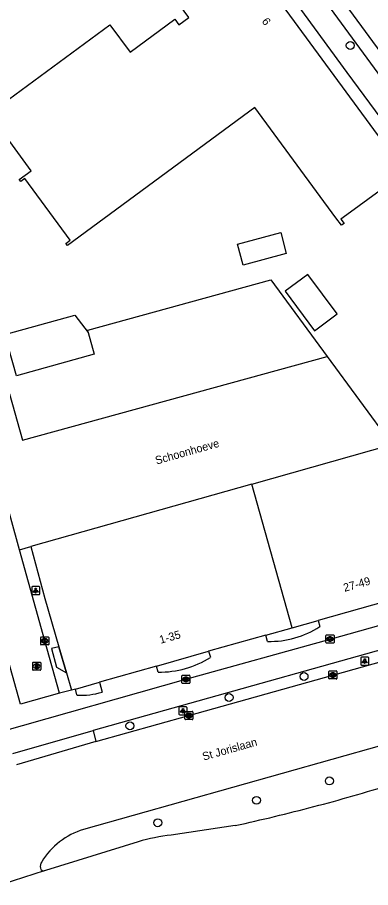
# Model space of a CAD drawing. Extents: x 161801 to 162379, y 382315 to 382832.
# Drawn here: x 161942.5 to 161986.3, y 382338.2 to 382446.1 of the extents above; entities that cross this region are included whole.
import ezdxf

# ---------------------------------------------------------------- set-up
doc = ezdxf.new("R2010")
doc.units = 0
for name, color, linetype in [('IMGEO_Boom', 7, 'Continuous'), ('IMGEO_Fietspad_open', 7, 'Continuous'), ('IMGEO_Hek', 7, 'Continuous'), ('IMGEO_Kolk', 7, 'Continuous'), ('IMGEO_Lichtpunt', 7, 'Continuous'), ('IMGEO_Openbare_ruimte_label', 7, 'Continuous'), ('IMGEO_Pand', 7, 'Continuous'), ('IMGEO_Pand_nummerreeks', 7, 'Continuous'), ('IMGEO_Pand_overbouw', 7, 'Continuous'), ('IMGEO_Parkeervlak_open', 7, 'Continuous'), ('IMGEO_Rijbaan_lokaal_gesloten', 7, 'Continuous'), ('IMGEO_Rijbaan_lokaal_open', 7, 'Continuous'), ('IMGEO_Rioolput', 7, 'Continuous'), ('IMGEO_Voetpad_open', 7, 'Continuous')]:
    doc.layers.add(name, color=color, linetype=linetype)

msp = doc.modelspace()

# ---------------------------------------------------------------- linework, layer by layer
at = {"layer": 'IMGEO_Boom'}
for centre in [(161983.8, 382442.62), (161978.07, 382364.4), (161968.77, 382361.8), (161956.46, 382358.28), (161981.22, 382351.46), (161972.17, 382349.05), (161959.92, 382346.27)]:
    msp.add_circle(centre, 0.489, dxfattribs=at)
at = {"layer": 'IMGEO_Fietspad_open'}
for points in [[(161923.26, 382352.78), (161924.44, 382353.11), (161940.37, 382357.56), (161963.41, 382364.05), (161981.29, 382369.04), (162000, 382374.27), (162016.84, 382378.99), (162027.28, 382381.95)], [(162003.49, 382372.17), (162002.74, 382371.95), (162000, 382371.17), (161951.89, 382357.7)], [(161941.94, 382354.87), (161951.89, 382357.7)]]:
    msp.add_lwpolyline(points, dxfattribs=at)
at = {"layer": 'IMGEO_Hek'}
for points in [[(161980.93, 382404.08), (161988.98, 382393.14)], [(161942.76, 382380.12), (161944.18, 382380.53)]]:
    msp.add_lwpolyline(points, dxfattribs=at)
at = {"layer": 'IMGEO_Kolk'}
for p, q in [((161980.79, 382368.62), (161980.79, 382369.47)), ((161980.87, 382369.55), (161981.72, 382369.55)), ((161981.79, 382369.47), (161981.79, 382368.62)), ((161945.39, 382368.38), (161945.39, 382369.23)), ((161945.47, 382369.31), (161946.32, 382369.31)), ((161946.32, 382368.31), (161945.47, 382368.31)), ((161945.88, 382369.09), (161945.91, 382369.09)), ((161945.9, 382368.53), (161945.88, 382368.53)), ((161946.4, 382369.23), (161946.4, 382368.38)), ((161981.72, 382368.55), (161980.87, 382368.55)), ((161981.28, 382369.33), (161981.31, 382369.33)), ((161981.3, 382368.77), (161981.28, 382368.77)), ((161981.22, 382365.09), (161982.07, 382365.09)), ((161962.91, 382363.63), (161962.91, 382364.48)), ((161962.98, 382364.55), (161963.84, 382364.55)), ((161963.4, 382364.33), (161963.42, 382364.33)), ((161963.91, 382364.48), (161963.91, 382363.63)), ((161981.14, 382364.16), (161981.14, 382365.01)), ((161982.07, 382364.09), (161981.22, 382364.09)), ((161981.63, 382364.87), (161981.66, 382364.87)), ((161981.65, 382364.31), (161981.63, 382364.31)), ((161982.14, 382365.01), (161982.14, 382364.16)), ((161963.84, 382363.55), (161962.98, 382363.55)), ((161963.42, 382363.77), (161963.39, 382363.77)), ((161963.28, 382359.14), (161963.28, 382359.99)), ((161963.35, 382360.07), (161964.21, 382360.07)), ((161963.77, 382359.84), (161963.79, 382359.84)), ((161964.28, 382359.99), (161964.28, 382359.14)), ((161964.21, 382359.06), (161963.35, 382359.06)), ((161963.79, 382359.29), (161963.76, 382359.29))]:
    msp.add_line(p, q, dxfattribs=at)
for points in [[(161980.79, 382368.62), (161980.79, 382369.47)], [(161980.87, 382369.55), (161981.72, 382369.55)], [(161981.79, 382369.47), (161981.79, 382368.62)], [(161945.39, 382368.38), (161945.39, 382369.23)], [(161945.47, 382369.31), (161946.32, 382369.31)], [(161946.32, 382368.31), (161945.47, 382368.31)], [(161945.71, 382369.01), (161945.84, 382369.01), (161945.84, 382368.86), (161945.97, 382369.01), (161946.13, 382369.01), (161945.99, 382368.86), (161946.14, 382368.61), (161945.99, 382368.61), (161945.9, 382368.77), (161945.84, 382368.71), (161945.84, 382368.61), (161945.71, 382368.61), (161945.71, 382369.01)], [(161946.4, 382369.23), (161946.4, 382368.38)], [(161981.72, 382368.55), (161980.87, 382368.55)], [(161981.11, 382369.25), (161981.24, 382369.25), (161981.24, 382369.09), (161981.37, 382369.25), (161981.53, 382369.25), (161981.39, 382369.1), (161981.54, 382368.85), (161981.39, 382368.85), (161981.3, 382369.01), (161981.24, 382368.94), (161981.24, 382368.85), (161981.11, 382368.85), (161981.11, 382369.25)], [(161981.22, 382365.09), (161982.07, 382365.09)], [(161962.91, 382363.63), (161962.91, 382364.48)], [(161962.98, 382364.55), (161963.84, 382364.55)], [(161963.23, 382364.25), (161963.35, 382364.25), (161963.35, 382364.1), (161963.48, 382364.25), (161963.65, 382364.25), (161963.5, 382364.1), (161963.65, 382363.85), (161963.5, 382363.85), (161963.42, 382364.02), (161963.35, 382363.95), (161963.35, 382363.85), (161963.23, 382363.85), (161963.23, 382364.25)], [(161963.91, 382364.48), (161963.91, 382363.63)], [(161981.14, 382364.16), (161981.14, 382365.01)], [(161982.07, 382364.09), (161981.22, 382364.09)], [(161981.46, 382364.79), (161981.59, 382364.79), (161981.59, 382364.63), (161981.72, 382364.79), (161981.88, 382364.79), (161981.74, 382364.64), (161981.89, 382364.39), (161981.74, 382364.39), (161981.65, 382364.55), (161981.59, 382364.48), (161981.59, 382364.39), (161981.46, 382364.39), (161981.46, 382364.79)], [(161982.14, 382365.01), (161982.14, 382364.16)], [(161963.84, 382363.55), (161962.98, 382363.55)], [(161963.28, 382359.14), (161963.28, 382359.99)], [(161963.35, 382360.07), (161964.21, 382360.07)], [(161963.6, 382359.76), (161963.72, 382359.76), (161963.72, 382359.61), (161963.85, 382359.76), (161964.02, 382359.76), (161963.87, 382359.61), (161964.02, 382359.36), (161963.87, 382359.36), (161963.79, 382359.53), (161963.72, 382359.46), (161963.72, 382359.36), (161963.6, 382359.36), (161963.6, 382359.76)], [(161964.28, 382359.99), (161964.28, 382359.14)], [(161964.21, 382359.06), (161963.35, 382359.06)]]:
    msp.add_lwpolyline(points, dxfattribs=at)
for centre, start, end in [((161980.87, 382369.47), 91.552, 178.448), ((161980.87, 382369.47), 91.552, 178.448), ((161981.72, 382369.47), 1.552, 88.448), ((161981.72, 382369.47), 1.552, 88.448), ((161945.47, 382369.23), 91.552, 178.448), ((161945.47, 382369.23), 91.552, 178.448), ((161945.47, 382368.38), 181.552, 268.448), ((161945.47, 382368.38), 181.552, 268.448), ((161946.32, 382369.23), 1.552, 88.448), ((161946.32, 382369.23), 1.552, 88.448), ((161946.32, 382368.38), 271.552, 358.448), ((161946.32, 382368.38), 271.552, 358.448), ((161980.87, 382368.62), 181.552, 268.448), ((161980.87, 382368.62), 181.552, 268.448), ((161981.72, 382368.62), 271.552, 358.448), ((161981.72, 382368.62), 271.552, 358.448), ((161981.22, 382365.01), 91.552, 178.448), ((161981.22, 382365.01), 91.552, 178.448), ((161982.07, 382365.01), 1.552, 88.448), ((161982.07, 382365.01), 1.552, 88.448), ((161962.99, 382364.48), 91.552, 178.448), ((161962.99, 382364.48), 91.552, 178.448), ((161963.83, 382364.48), 1.552, 88.448), ((161963.83, 382364.48), 1.552, 88.448), ((161981.22, 382364.16), 181.552, 268.448), ((161981.22, 382364.16), 181.552, 268.448), ((161982.07, 382364.16), 271.552, 358.448), ((161982.07, 382364.16), 271.552, 358.448), ((161962.99, 382363.63), 181.552, 268.448), ((161962.99, 382363.63), 181.552, 268.448), ((161963.83, 382363.63), 271.552, 358.448), ((161963.83, 382363.63), 271.552, 358.448), ((161963.36, 382359.99), 91.552, 178.448), ((161963.36, 382359.99), 91.552, 178.448), ((161964.2, 382359.99), 1.552, 88.448), ((161964.2, 382359.99), 1.552, 88.448), ((161963.36, 382359.14), 181.552, 268.448), ((161963.36, 382359.14), 181.552, 268.448), ((161964.2, 382359.14), 271.552, 358.448), ((161964.2, 382359.14), 271.552, 358.448)]:
    msp.add_arc(centre, 0.0765, start, end, dxfattribs=at)
for centre, major_axis, ratio, start_param, end_param in [((161945.88, 382368.81), (-0.387, 0.002), 0.722429, 4.712389, 7.853982), ((161945.91, 382368.81), (-0.39, 0.002), 0.717154, 1.570796, 4.712389), ((161981.28, 382369.05), (-0.387, 0.002), 0.722429, 4.712389, 7.853982), ((161981.3, 382369.05), (-0.39, 0.002), 0.717154, 1.570796, 4.712389), ((161963.4, 382364.05), (-0.387, 0.002), 0.722429, 4.712389, 7.853982), ((161963.42, 382364.05), (-0.39, 0.002), 0.717154, 1.570796, 4.712389), ((161981.63, 382364.59), (-0.387, 0.002), 0.722429, 4.712389, 7.853982), ((161981.65, 382364.59), (-0.39, 0.002), 0.717154, 1.570796, 4.712389), ((161963.77, 382359.56), (-0.387, 0.002), 0.722429, 4.712389, 7.853982), ((161963.79, 382359.56), (-0.39, 0.002), 0.717154, 1.570796, 4.712389)]:
    msp.add_ellipse(centre, major_axis=major_axis, ratio=ratio, start_param=start_param, end_param=end_param, dxfattribs=at)
at = {"layer": 'IMGEO_Lichtpunt'}
for p, q in [((161944.27, 382375.46), (161944.27, 382374.65)), ((161944.27, 382375.46), (161944.27, 382374.65)), ((161945.18, 382375.55), (161944.37, 382375.55)), ((161945.18, 382375.55), (161944.37, 382375.55)), ((161945.27, 382374.65), (161945.27, 382375.46)), ((161945.27, 382374.65), (161945.27, 382375.46)), ((161944.37, 382374.56), (161945.18, 382374.56)), ((161944.37, 382374.56), (161945.18, 382374.56)), ((161985.11, 382366.7), (161985.11, 382365.9)), ((161985.11, 382366.7), (161985.11, 382365.9)), ((161986.01, 382366.8), (161985.2, 382366.8)), ((161986.01, 382366.8), (161985.2, 382366.8)), ((161986.11, 382365.9), (161986.11, 382366.7)), ((161986.11, 382365.9), (161986.11, 382366.7)), ((161985.2, 382365.8), (161986.01, 382365.8)), ((161985.2, 382365.8), (161986.01, 382365.8)), ((161962.55, 382360.55), (161962.55, 382359.75)), ((161962.55, 382360.55), (161962.55, 382359.75)), ((161963.45, 382360.65), (161962.64, 382360.65)), ((161963.45, 382360.65), (161962.64, 382360.65)), ((161962.64, 382359.65), (161963.45, 382359.65)), ((161962.64, 382359.65), (161963.45, 382359.65)), ((161963.55, 382359.75), (161963.55, 382360.55)), ((161963.55, 382359.75), (161963.55, 382360.55))]:
    msp.add_line(p, q, dxfattribs=at)
for points in [[(161944.65, 382375.12), (161944.69, 382375.1), (161944.5, 382374.83), (161944.46, 382374.86), (161944.65, 382375.12)], [(161944.75, 382375.08), (161944.8, 382375.08), (161944.8, 382374.75), (161944.75, 382374.75), (161944.75, 382375.08)], [(161944.86, 382375.1), (161944.9, 382375.12), (161945.09, 382374.86), (161945.05, 382374.83), (161944.86, 382375.1)], [(161985.48, 382366.37), (161985.52, 382366.34), (161985.33, 382366.08), (161985.3, 382366.1), (161985.48, 382366.37)], [(161985.58, 382366.32), (161985.63, 382366.32), (161985.63, 382366), (161985.58, 382366), (161985.58, 382366.32)], [(161985.69, 382366.34), (161985.73, 382366.37), (161985.92, 382366.1), (161985.88, 382366.08), (161985.69, 382366.34)], [(161962.92, 382360.22), (161962.96, 382360.19), (161962.77, 382359.93), (161962.74, 382359.96), (161962.92, 382360.22)], [(161963.02, 382360.17), (161963.07, 382360.17), (161963.07, 382359.85), (161963.02, 382359.85), (161963.02, 382360.17)], [(161963.13, 382360.19), (161963.17, 382360.22), (161963.36, 382359.95), (161963.32, 382359.93), (161963.13, 382360.19)]]:
    msp.add_lwpolyline(points, dxfattribs=at)
for centre in [(161944.77, 382375.26), (161985.61, 382366.5), (161963.05, 382360.35)]:
    msp.add_circle(centre, 0.0994, dxfattribs=at)
for centre, start, end in [((161944.37, 382375.46), 90, 180), ((161944.37, 382375.46), 90, 180), ((161945.18, 382375.46), 0, 90), ((161945.18, 382375.46), 0, 90), ((161944.37, 382374.65), 180, 270), ((161944.37, 382374.65), 180, 270), ((161945.18, 382374.65), 270, 0), ((161945.18, 382374.65), 270, 360), ((161985.2, 382366.7), 90, 180), ((161985.2, 382366.7), 90, 180), ((161986.01, 382366.7), 0, 90), ((161986.01, 382366.7), 0, 90), ((161985.2, 382365.9), 180, 270), ((161985.2, 382365.9), 180, 270), ((161986.01, 382365.9), 270, 0), ((161986.01, 382365.9), 270, 360), ((161962.64, 382360.55), 90, 180), ((161962.64, 382360.55), 90, 180), ((161962.64, 382359.75), 180, 270), ((161962.64, 382359.75), 180, 270), ((161963.45, 382360.55), 0, 90), ((161963.45, 382360.55), 0, 90), ((161963.45, 382359.75), 270, 0), ((161963.45, 382359.75), 270, 360)]:
    msp.add_arc(centre, 0.0946, start, end, dxfattribs=at)
at = {"layer": 'IMGEO_Pand'}
for points in [[(161958.96, 382469.92), (161992.2, 382424.73), (161989.12, 382422.47), (161987.51, 382424.66), (161983.38, 382421.62), (161982.64, 382421.08), (161983.03, 382420.56), (161982.71, 382420.33), (161982.03, 382421.26), (161971.98, 382434.92)], [(161971.98, 382434.92), (161953.28, 382421.17), (161948.72, 382417.82), (161948.53, 382418.08), (161949.06, 382418.47), (161943.43, 382426.13), (161942.91, 382425.75), (161942.72, 382426.01), (161944.2, 382427.09), (161938.98, 382434.18), (161953.97, 382445.2), (161956.48, 382441.78), (161962.04, 382445.87), (161962.55, 382445.18), (161963.79, 382446.1), (161956.29, 382456.29)], [(161975.87, 382416.82), (161970.52, 382415.39), (161969.82, 382417.99), (161975.17, 382419.42), (161975.87, 382416.82)], [(161979.37, 382407.26), (161982.18, 382409.35), (161978.54, 382414.25), (161975.73, 382412.16), (161979.37, 382407.26)], [(161951.3, 382407.05), (161951.23, 382407.32), (161973.95, 382413.57), (161980.93, 382404.08)], [(161942.37, 382401.68), (161940.94, 382406.8), (161949.61, 382409.21), (161951.3, 382407.05)], [(161951.3, 382407.05), (161952.02, 382404.36), (161942.37, 382401.68)], [(161941.52, 382399.44), (161943.12, 382393.68), (161980.93, 382404.08)], [(161971.57, 382388.24), (161988.98, 382393.14)], [(161971.57, 382388.24), (161944.18, 382380.53)], [(161976.58, 382370.43), (161971.57, 382388.24)], [(161944.18, 382380.53), (161945.9, 382374.07), (161947.64, 382368.08)], [(161991.7, 382374.69), (161979.83, 382371.34)], [(161976.58, 382370.43), (161979.83, 382371.34)], [(161973.33, 382369.52), (161966.23, 382367.52)], [(161973.33, 382369.52), (161976.58, 382370.43)], [(161947.64, 382368.08), (161948.58, 382364.87)], [(161959.74, 382365.7), (161966.23, 382367.52)], [(161959.74, 382365.7), (161952.67, 382363.71)], [(161948.58, 382364.87), (161949.21, 382362.71)], [(161949.69, 382362.85), (161952.67, 382363.71)], [(161949.69, 382362.85), (161949.21, 382362.71)]]:
    msp.add_lwpolyline(points, dxfattribs=at)
at = {"layer": 'IMGEO_Pand_overbouw'}
msp.add_lwpolyline([(161947.64, 382368.08), (161946.72, 382367.85), (161947.36, 382365.56), (161948.58, 382364.87)], close=True, dxfattribs=at)
at = {"layer": 'IMGEO_Parkeervlak_open'}
msp.add_lwpolyline([(161980.93, 382404.08), (161988.98, 382393.14)], dxfattribs=at)
at = {"layer": 'IMGEO_Rijbaan_lokaal_gesloten'}
for points in [[(161952.25, 382356.34), (161963.78, 382359.56), (161981.64, 382364.58), (161999.31, 382369.52), (162001.65, 382370.15), (162004.08, 382370.35)], [(162003.12, 382360.19), (162000, 382359.32), (161950.69, 382345.43)], [(161952.25, 382356.34), (161942.38, 382353.46)], [(161969.54, 382345.92), (161961.59, 382344.75)], [(161957.49, 382343.92), (161945.97, 382340.35), (161945.82, 382340.3)], [(161945.82, 382340.3), (161939.36, 382338.23)]]:
    msp.add_lwpolyline(points, dxfattribs=at)
for centre, radius, start, end in [((161916.07, 382587.59), 247.53, 284.7969, 287.1221), ((161916.1, 382589.53), 249.4, 282.3713, 284.6762), ((161953.43, 382336.56), 9.29, 107.1293, 148.3563), ((161964.76, 382318.42), 26.52, 96.8686, 105.9125), ((161946.35, 382340.85), 1.01, 144.7481, 191.7675), ((161945.77, 382340.72), 0.422, 190.5381, 276.4398)]:
    msp.add_arc(centre, radius, start, end, dxfattribs=at)
at = {"layer": 'IMGEO_Rijbaan_lokaal_open'}
for points in [[(161966.54, 382470.38), (161996.41, 382429.74)], [(161947.71, 382362.34), (161942.87, 382360.97), (161940.59, 382369.12), (161932.13, 382399.26)], [(161942.76, 382380.12), (161939.23, 382392.79)], [(161947.71, 382362.34), (161945.9, 382368.81), (161942.76, 382380.12)]]:
    msp.add_lwpolyline(points, dxfattribs=at)
at = {"layer": 'IMGEO_Rioolput'}
for p, q in [((161944.47, 382366.18), (161945.32, 382366.18)), ((161944.4, 382365.25), (161944.4, 382366.1)), ((161945.32, 382365.18), (161944.47, 382365.18)), ((161944.91, 382365.4), (161944.88, 382365.4)), ((161944.89, 382365.96), (161944.91, 382365.96)), ((161945.4, 382366.1), (161945.4, 382365.25))]:
    msp.add_line(p, q, dxfattribs=at)
for points in [[(161944.47, 382366.18), (161945.32, 382366.18)], [(161944.4, 382365.25), (161944.4, 382366.1)], [(161945.32, 382365.18), (161944.47, 382365.18)], [(161944.99, 382365.87), (161944.73, 382365.88), (161944.73, 382365.48)], [(161944.73, 382365.48), (161944.86, 382365.48), (161944.86, 382365.64), (161944.87, 382365.64)], [(161944.91, 382365.8), (161944.86, 382365.8), (161944.86, 382365.71)], [(161944.86, 382365.71), (161944.91, 382365.71)], [(161944.92, 382365.61), (161944.99, 382365.48), (161945.13, 382365.48), (161945.06, 382365.6)], [(161945.4, 382366.1), (161945.4, 382365.25)]]:
    msp.add_lwpolyline(points, dxfattribs=at)
for centre, radius, start, end in [((161944.47, 382366.1), 0.0765, 91.552, 178.448), ((161944.47, 382366.1), 0.0765, 91.552, 178.448), ((161945.32, 382366.1), 0.0765, 1.552, 88.448), ((161945.32, 382366.1), 0.0765, 1.552, 88.448), ((161944.47, 382365.25), 0.0765, 181.552, 268.448), ((161944.47, 382365.25), 0.0765, 181.552, 268.448), ((161944.87, 382365.59), 0.0533, 26.0293, 88.6989), ((161944.92, 382365.7), 0.0964, 77.0061, 93.1865), ((161944.89, 382365.9), 0.19, 274.7715, 282.9687), ((161944.93, 382365.76), 0.0378, 276.6634, 79.6772), ((161944.99, 382365.76), 0.109, 350.3612, 89.416), ((161944.98, 382365.76), 0.112, 277.5842, 350.9817), ((161944.97, 382365.55), 0.108, 29.5134, 73.7905), ((161945.32, 382365.25), 0.0765, 271.552, 358.448), ((161945.32, 382365.25), 0.0765, 271.552, 358.448)]:
    msp.add_arc(centre, radius, start, end, dxfattribs=at)
for centre, major_axis, ratio, start_param, end_param in [((161944.88, 382365.68), (-0.387, 0.002), 0.722429, 4.712389, 7.853982), ((161944.91, 382365.68), (-0.39, 0.002), 0.717154, 1.570796, 4.712389)]:
    msp.add_ellipse(centre, major_axis=major_axis, ratio=ratio, start_param=start_param, end_param=end_param, dxfattribs=at)
at = {"layer": 'IMGEO_Voetpad_open'}
for points in [[(161998.06, 382419.48), (161983.4, 382439.27), (161954.73, 382478.54)], [(161993.32, 382430.95), (161966.55, 382467.45)], [(161942.76, 382380.12), (161944.18, 382380.53)], [(161979.83, 382371.34), (161980.04, 382370.58)], [(161973.55, 382368.75), (161973.33, 382369.52)], [(161947.64, 382368.08), (161946.72, 382367.85), (161947.36, 382365.56), (161948.58, 382364.87)], [(161966.23, 382367.52), (161966.46, 382366.78)], [(161959.97, 382364.95), (161959.74, 382365.7)], [(161952.67, 382363.71), (161953.01, 382362.47)], [(161949.21, 382362.71), (161947.71, 382362.34)], [(161949.89, 382362.11), (161949.69, 382362.85)], [(161951.89, 382357.7), (161952.25, 382356.34)]]:
    msp.add_lwpolyline(points, dxfattribs=at)
for centre, radius, start, end in [((161973.84, 382380.18), 11.43, 268.5533, 302.8517), ((161960.2, 382376.58), 11.63, 268.8553, 302.5216), ((161950.44, 382370.93), 8.85, 266.45, 286.8993)]:
    msp.add_arc(centre, radius, start, end, dxfattribs=at)

# ---------------------------------------------------------------- texts
at = {"layer": 'IMGEO_Openbare_ruimte_label'}
for s, rotation, p in [('Schoonhoeve', 15.7879, (161959.76, 382390.67)), ('St Jorislaan', 15.7328, (161965.61, 382353.97))]:
    msp.add_text(s, height=1, rotation=rotation, dxfattribs=at).set_placement(p)
at = {"layer": 'IMGEO_Pand_nummerreeks'}
for s, rotation, p in [('6', 306.3364, (161972.77, 382445.61)), ('27-49', 15.7445, (161983.1, 382374.89)), ('1-35', 15.7399, (161960.27, 382368.45))]:
    msp.add_text(s, height=1, rotation=rotation, dxfattribs=at).set_placement(p)

doc.saveas('drawing.dxf')
